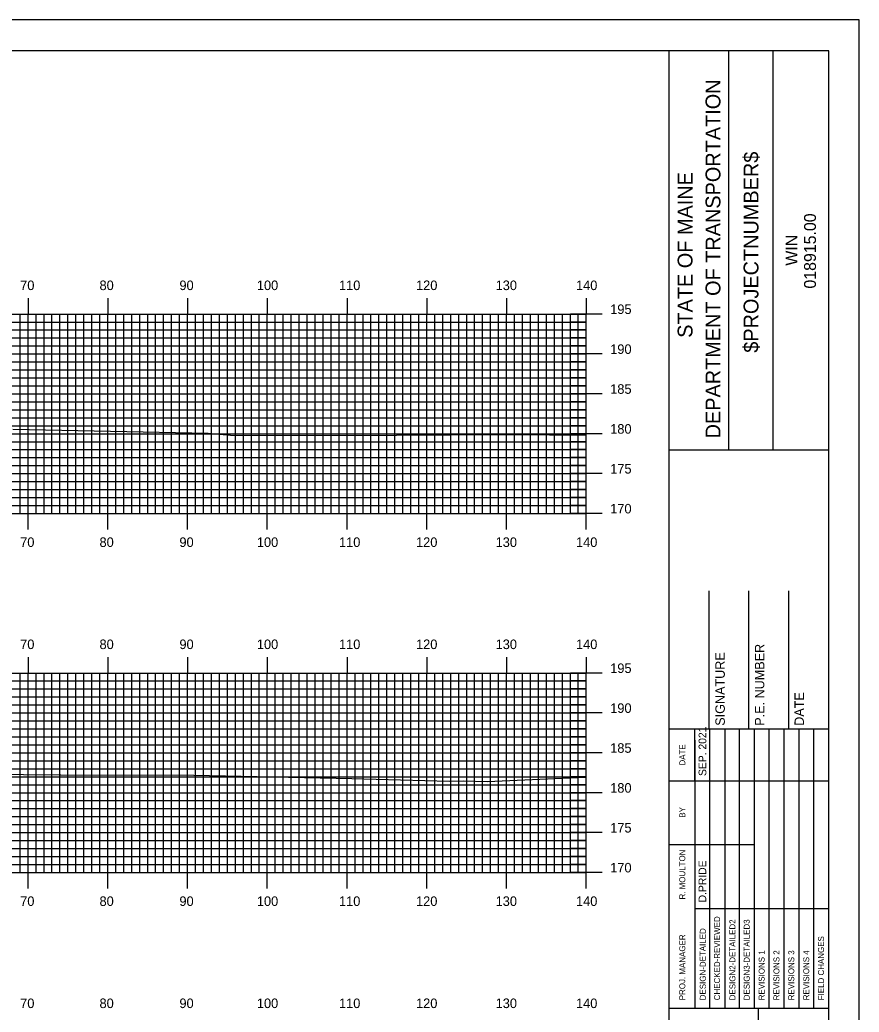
# Model space of a CAD drawing. Extents: x 1824360 to 1824703, y 442591 to 442811.
# Drawn here: x 1824594.3 to 1824699.5, y 442686.2 to 442810.5 of the extents above; entities that cross this region are included whole.
import ezdxf

# ---------------------------------------------------------------- set-up
doc = ezdxf.new("R2010")
doc.units = 0
for name, color, linetype in [('BORDER', 7, 'Continuous'), ('H_V ANNOTATION', 7, 'Continuous'), ('MAJOR', 7, 'Continuous'), ('MINOR', 7, 'Continuous'), ('PLOT BOUNDARY', 7, 'Continuous'), ('S_Roadway_Centerline', 7, 'Continuous')]:
    doc.layers.add(name, color=color, linetype=linetype)

msp = doc.modelspace()

# ---------------------------------------------------------------- linework, layer by layer
at = {"layer": 'BORDER'}
for p, q in [((1824675.73, 442596.67), (1824675.73, 442806.67)), ((1824683.19, 442756.66), (1824683.19, 442806.66)), ((1824688.78, 442756.66), (1824688.78, 442806.66)), ((1824675.74, 442756.65), (1824695.73, 442756.65)), ((1824680.73, 442721.67), (1824680.73, 442738.97)), ((1824685.73, 442721.67), (1824685.73, 442738.97)), ((1824690.73, 442721.67), (1824690.73, 442738.97)), ((1824675.73, 442721.67), (1824695.73, 442721.67)), ((1824675.73, 442686.67), (1824695.73, 442686.67)), ((1824686.92, 442616.67), (1824686.92, 442686.67))]:
    msp.add_line(p, q, dxfattribs=at)
msp.add_lwpolyline([(1824375.73, 442596.67), (1824695.73, 442596.67), (1824695.73, 442806.67), (1824375.73, 442806.67)], close=True, dxfattribs=at)
for points in [[(1824678.96, 442715.17), (1824678.96, 442721.67)], [(1824680.83, 442686.68), (1824680.83, 442721.67)], [(1824682.69, 442721.67), (1824682.69, 442686.68)], [(1824684.56, 442686.68), (1824684.56, 442721.67)], [(1824686.42, 442686.68), (1824686.42, 442721.67)], [(1824688.28, 442686.68), (1824688.28, 442721.67)], [(1824690.15, 442686.68), (1824690.15, 442721.67)], [(1824692.01, 442686.68), (1824692.01, 442721.67)], [(1824693.87, 442686.68), (1824693.87, 442721.67)], [(1824678.97, 442686.68), (1824678.97, 442720.26)], [(1824675.73, 442715.17), (1824695.73, 442715.17)], [(1824675.73, 442707.17), (1824678.97, 442707.17)], [(1824678.96, 442707.17), (1824686.42, 442707.17)], [(1824678.96, 442699.17), (1824695.73, 442699.17)]]:
    msp.add_lwpolyline(points, dxfattribs=at)
at = {"layer": 'MAJOR'}
for p, q in [((1824595.33, 442775.67), (1824595.33, 442773.67)), ((1824605.33, 442775.67), (1824605.33, 442773.67)), ((1824615.33, 442775.67), (1824615.33, 442773.67)), ((1824625.33, 442775.67), (1824625.33, 442773.67)), ((1824635.33, 442775.67), (1824635.33, 442773.67)), ((1824645.33, 442775.67), (1824645.33, 442773.67)), ((1824655.33, 442775.67), (1824655.33, 442773.67)), ((1824665.33, 442775.67), (1824665.33, 442773.67)), ((1824385.33, 442773.67), (1824665.33, 442773.67)), ((1824385.33, 442773.67), (1824665.33, 442773.67)), ((1824595.33, 442748.67), (1824595.33, 442773.67)), ((1824605.33, 442748.67), (1824605.33, 442773.67)), ((1824615.33, 442748.67), (1824615.33, 442773.67)), ((1824625.33, 442748.67), (1824625.33, 442773.67)), ((1824635.33, 442748.67), (1824635.33, 442773.67)), ((1824645.33, 442748.67), (1824645.33, 442773.67)), ((1824655.33, 442748.67), (1824655.33, 442773.67)), ((1824667.34, 442773.67), (1824663.33, 442773.67)), ((1824665.33, 442748.67), (1824665.33, 442773.67)), ((1824665.33, 442748.67), (1824665.33, 442773.67)), ((1824385.33, 442768.67), (1824665.33, 442768.67)), ((1824667.34, 442768.67), (1824663.33, 442768.67)), ((1824385.33, 442763.67), (1824665.33, 442763.67)), ((1824667.34, 442763.67), (1824663.33, 442763.67)), ((1824385.33, 442758.67), (1824665.33, 442758.67)), ((1824667.34, 442758.67), (1824663.33, 442758.67)), ((1824385.33, 442753.67), (1824665.33, 442753.67)), ((1824667.34, 442753.67), (1824663.33, 442753.67)), ((1824385.33, 442748.67), (1824665.33, 442748.67)), ((1824385.33, 442748.67), (1824665.33, 442748.67)), ((1824595.33, 442746.66), (1824595.33, 442748.67)), ((1824605.33, 442746.66), (1824605.33, 442748.67)), ((1824615.33, 442746.66), (1824615.33, 442748.67)), ((1824625.33, 442746.66), (1824625.33, 442748.67)), ((1824635.33, 442746.66), (1824635.33, 442748.67)), ((1824645.33, 442746.66), (1824645.33, 442748.67)), ((1824655.33, 442746.66), (1824655.33, 442748.67)), ((1824667.34, 442748.67), (1824663.33, 442748.67)), ((1824665.33, 442746.66), (1824665.33, 442748.67)), ((1824595.33, 442730.67), (1824595.33, 442728.67)), ((1824605.33, 442730.67), (1824605.33, 442728.67)), ((1824615.33, 442730.67), (1824615.33, 442728.67)), ((1824625.33, 442730.67), (1824625.33, 442728.67)), ((1824635.33, 442730.67), (1824635.33, 442728.67)), ((1824645.33, 442730.67), (1824645.33, 442728.67)), ((1824655.33, 442730.67), (1824655.33, 442728.67)), ((1824665.33, 442730.67), (1824665.33, 442728.67)), ((1824385.33, 442728.67), (1824665.33, 442728.67)), ((1824385.33, 442728.67), (1824665.33, 442728.67)), ((1824595.33, 442703.67), (1824595.33, 442728.67)), ((1824605.33, 442703.67), (1824605.33, 442728.67)), ((1824615.33, 442703.67), (1824615.33, 442728.67)), ((1824625.33, 442703.67), (1824625.33, 442728.67)), ((1824635.33, 442703.67), (1824635.33, 442728.67)), ((1824645.33, 442703.67), (1824645.33, 442728.67)), ((1824655.33, 442703.67), (1824655.33, 442728.67)), ((1824667.34, 442728.67), (1824663.33, 442728.67)), ((1824665.33, 442703.67), (1824665.33, 442728.67)), ((1824665.33, 442703.67), (1824665.33, 442728.67)), ((1824385.33, 442723.67), (1824665.33, 442723.67)), ((1824667.34, 442723.67), (1824663.33, 442723.67)), ((1824385.33, 442718.67), (1824665.33, 442718.67)), ((1824667.34, 442718.67), (1824663.33, 442718.67)), ((1824385.33, 442713.67), (1824665.33, 442713.67)), ((1824667.34, 442713.67), (1824663.33, 442713.67)), ((1824385.33, 442708.67), (1824665.33, 442708.67)), ((1824667.34, 442708.67), (1824663.33, 442708.67)), ((1824385.33, 442703.67), (1824665.33, 442703.67)), ((1824385.33, 442703.67), (1824665.33, 442703.67)), ((1824595.33, 442701.66), (1824595.33, 442703.67)), ((1824605.33, 442701.66), (1824605.33, 442703.67)), ((1824615.33, 442701.66), (1824615.33, 442703.67)), ((1824625.33, 442701.66), (1824625.33, 442703.67)), ((1824635.33, 442701.66), (1824635.33, 442703.67)), ((1824645.33, 442701.66), (1824645.33, 442703.67)), ((1824655.33, 442701.66), (1824655.33, 442703.67)), ((1824667.34, 442703.67), (1824663.33, 442703.67)), ((1824665.33, 442701.66), (1824665.33, 442703.67))]:
    msp.add_line(p, q, dxfattribs=at)
at = {"layer": 'MINOR'}
for p, q in [((1824594.33, 442748.67), (1824594.33, 442773.67)), ((1824596.33, 442748.67), (1824596.33, 442773.67)), ((1824597.33, 442748.67), (1824597.33, 442773.67)), ((1824598.33, 442748.67), (1824598.33, 442773.67)), ((1824599.33, 442748.67), (1824599.33, 442773.67)), ((1824600.33, 442748.67), (1824600.33, 442773.67)), ((1824601.33, 442748.67), (1824601.33, 442773.67)), ((1824602.33, 442748.67), (1824602.33, 442773.67)), ((1824603.33, 442748.67), (1824603.33, 442773.67)), ((1824604.33, 442748.67), (1824604.33, 442773.67)), ((1824606.33, 442748.67), (1824606.33, 442773.67)), ((1824607.33, 442748.67), (1824607.33, 442773.67)), ((1824608.33, 442748.67), (1824608.33, 442773.67)), ((1824609.33, 442748.67), (1824609.33, 442773.67)), ((1824610.33, 442748.67), (1824610.33, 442773.67)), ((1824611.33, 442748.67), (1824611.33, 442773.67)), ((1824612.33, 442748.67), (1824612.33, 442773.67)), ((1824613.33, 442748.67), (1824613.33, 442773.67)), ((1824614.33, 442748.67), (1824614.33, 442773.67)), ((1824616.33, 442748.67), (1824616.33, 442773.67)), ((1824617.33, 442748.67), (1824617.33, 442773.67)), ((1824618.33, 442748.67), (1824618.33, 442773.67)), ((1824619.33, 442748.67), (1824619.33, 442773.67)), ((1824620.33, 442748.67), (1824620.33, 442773.67)), ((1824621.33, 442748.67), (1824621.33, 442773.67)), ((1824622.33, 442748.67), (1824622.33, 442773.67)), ((1824623.33, 442748.67), (1824623.33, 442773.67)), ((1824624.33, 442748.67), (1824624.33, 442773.67)), ((1824626.33, 442748.67), (1824626.33, 442773.67)), ((1824627.33, 442748.67), (1824627.33, 442773.67)), ((1824628.33, 442748.67), (1824628.33, 442773.67)), ((1824629.33, 442748.67), (1824629.33, 442773.67)), ((1824630.33, 442748.67), (1824630.33, 442773.67)), ((1824631.33, 442748.67), (1824631.33, 442773.67)), ((1824632.33, 442748.67), (1824632.33, 442773.67)), ((1824633.33, 442748.67), (1824633.33, 442773.67)), ((1824634.33, 442748.67), (1824634.33, 442773.67)), ((1824636.33, 442748.67), (1824636.33, 442773.67)), ((1824637.33, 442748.67), (1824637.33, 442773.67)), ((1824638.33, 442748.67), (1824638.33, 442773.67)), ((1824639.33, 442748.67), (1824639.33, 442773.67)), ((1824640.33, 442748.67), (1824640.33, 442773.67)), ((1824641.33, 442748.67), (1824641.33, 442773.67)), ((1824642.33, 442748.67), (1824642.33, 442773.67)), ((1824643.33, 442748.67), (1824643.33, 442773.67)), ((1824644.33, 442748.67), (1824644.33, 442773.67)), ((1824646.33, 442748.67), (1824646.33, 442773.67)), ((1824647.33, 442748.67), (1824647.33, 442773.67)), ((1824648.33, 442748.67), (1824648.33, 442773.67)), ((1824649.33, 442748.67), (1824649.33, 442773.67)), ((1824650.33, 442748.67), (1824650.33, 442773.67)), ((1824651.33, 442748.67), (1824651.33, 442773.67)), ((1824652.33, 442748.67), (1824652.33, 442773.67)), ((1824653.33, 442748.67), (1824653.33, 442773.67)), ((1824654.33, 442748.67), (1824654.33, 442773.67)), ((1824656.33, 442748.67), (1824656.33, 442773.67)), ((1824657.33, 442748.67), (1824657.33, 442773.67)), ((1824658.33, 442748.67), (1824658.33, 442773.67)), ((1824659.33, 442748.67), (1824659.33, 442773.67)), ((1824660.33, 442748.67), (1824660.33, 442773.67)), ((1824661.33, 442748.67), (1824661.33, 442773.67)), ((1824662.33, 442748.67), (1824662.33, 442773.67)), ((1824663.33, 442748.67), (1824663.33, 442773.67)), ((1824664.33, 442748.67), (1824664.33, 442773.67)), ((1824385.33, 442772.67), (1824665.33, 442772.67)), ((1824665.33, 442772.67), (1824663.33, 442772.67)), ((1824385.33, 442771.67), (1824665.33, 442771.67)), ((1824665.33, 442771.67), (1824663.33, 442771.67)), ((1824385.33, 442770.67), (1824665.33, 442770.67)), ((1824665.33, 442770.67), (1824663.33, 442770.67)), ((1824385.33, 442769.67), (1824665.33, 442769.67)), ((1824665.33, 442769.67), (1824663.33, 442769.67)), ((1824385.33, 442767.67), (1824665.33, 442767.67)), ((1824665.33, 442767.67), (1824663.33, 442767.67)), ((1824385.33, 442766.67), (1824665.33, 442766.67)), ((1824665.33, 442766.67), (1824663.33, 442766.67)), ((1824385.33, 442765.67), (1824665.33, 442765.67)), ((1824665.33, 442765.67), (1824663.33, 442765.67)), ((1824385.33, 442764.67), (1824665.33, 442764.67)), ((1824665.33, 442764.67), (1824663.33, 442764.67)), ((1824385.33, 442762.67), (1824665.33, 442762.67)), ((1824665.33, 442762.67), (1824663.33, 442762.67)), ((1824385.33, 442761.67), (1824665.33, 442761.67)), ((1824665.33, 442761.67), (1824663.33, 442761.67)), ((1824385.33, 442760.67), (1824665.33, 442760.67)), ((1824665.33, 442760.67), (1824663.33, 442760.67)), ((1824385.33, 442759.67), (1824665.33, 442759.67)), ((1824665.33, 442759.67), (1824663.33, 442759.67)), ((1824385.33, 442757.67), (1824665.33, 442757.67)), ((1824665.33, 442757.67), (1824663.33, 442757.67)), ((1824385.33, 442756.67), (1824665.33, 442756.67)), ((1824665.33, 442756.67), (1824663.33, 442756.67)), ((1824385.33, 442755.67), (1824665.33, 442755.67)), ((1824665.33, 442755.67), (1824663.33, 442755.67)), ((1824385.33, 442754.67), (1824665.33, 442754.67)), ((1824665.33, 442754.67), (1824663.33, 442754.67)), ((1824385.33, 442752.67), (1824665.33, 442752.67)), ((1824665.33, 442752.67), (1824663.33, 442752.67)), ((1824385.33, 442751.67), (1824665.33, 442751.67)), ((1824665.33, 442751.67), (1824663.33, 442751.67)), ((1824385.33, 442750.67), (1824665.33, 442750.67)), ((1824665.33, 442750.67), (1824663.33, 442750.67)), ((1824385.33, 442749.67), (1824665.33, 442749.67)), ((1824665.33, 442749.67), (1824663.33, 442749.67)), ((1824385.33, 442727.67), (1824665.33, 442727.67)), ((1824594.33, 442703.67), (1824594.33, 442728.67)), ((1824596.33, 442703.67), (1824596.33, 442728.67)), ((1824597.33, 442703.67), (1824597.33, 442728.67)), ((1824598.33, 442703.67), (1824598.33, 442728.67)), ((1824599.33, 442703.67), (1824599.33, 442728.67)), ((1824600.33, 442703.67), (1824600.33, 442728.67)), ((1824601.33, 442703.67), (1824601.33, 442728.67)), ((1824602.33, 442703.67), (1824602.33, 442728.67)), ((1824603.33, 442703.67), (1824603.33, 442728.67)), ((1824604.33, 442703.67), (1824604.33, 442728.67)), ((1824606.33, 442703.67), (1824606.33, 442728.67)), ((1824607.33, 442703.67), (1824607.33, 442728.67)), ((1824608.33, 442703.67), (1824608.33, 442728.67)), ((1824609.33, 442703.67), (1824609.33, 442728.67)), ((1824610.33, 442703.67), (1824610.33, 442728.67)), ((1824611.33, 442703.67), (1824611.33, 442728.67)), ((1824612.33, 442703.67), (1824612.33, 442728.67)), ((1824613.33, 442703.67), (1824613.33, 442728.67)), ((1824614.33, 442703.67), (1824614.33, 442728.67)), ((1824616.33, 442703.67), (1824616.33, 442728.67)), ((1824617.33, 442703.67), (1824617.33, 442728.67)), ((1824618.33, 442703.67), (1824618.33, 442728.67)), ((1824619.33, 442703.67), (1824619.33, 442728.67)), ((1824620.33, 442703.67), (1824620.33, 442728.67)), ((1824621.33, 442703.67), (1824621.33, 442728.67)), ((1824622.33, 442703.67), (1824622.33, 442728.67)), ((1824623.33, 442703.67), (1824623.33, 442728.67)), ((1824624.33, 442703.67), (1824624.33, 442728.67)), ((1824626.33, 442703.67), (1824626.33, 442728.67)), ((1824627.33, 442703.67), (1824627.33, 442728.67)), ((1824628.33, 442703.67), (1824628.33, 442728.67)), ((1824629.33, 442703.67), (1824629.33, 442728.67)), ((1824630.33, 442703.67), (1824630.33, 442728.67)), ((1824631.33, 442703.67), (1824631.33, 442728.67)), ((1824632.33, 442703.67), (1824632.33, 442728.67)), ((1824633.33, 442703.67), (1824633.33, 442728.67)), ((1824634.33, 442703.67), (1824634.33, 442728.67)), ((1824636.33, 442703.67), (1824636.33, 442728.67)), ((1824637.33, 442703.67), (1824637.33, 442728.67)), ((1824638.33, 442703.67), (1824638.33, 442728.67)), ((1824639.33, 442703.67), (1824639.33, 442728.67)), ((1824640.33, 442703.67), (1824640.33, 442728.67)), ((1824641.33, 442703.67), (1824641.33, 442728.67)), ((1824642.33, 442703.67), (1824642.33, 442728.67)), ((1824643.33, 442703.67), (1824643.33, 442728.67)), ((1824644.33, 442703.67), (1824644.33, 442728.67)), ((1824646.33, 442703.67), (1824646.33, 442728.67)), ((1824647.33, 442703.67), (1824647.33, 442728.67)), ((1824648.33, 442703.67), (1824648.33, 442728.67)), ((1824649.33, 442703.67), (1824649.33, 442728.67)), ((1824650.33, 442703.67), (1824650.33, 442728.67)), ((1824651.33, 442703.67), (1824651.33, 442728.67)), ((1824652.33, 442703.67), (1824652.33, 442728.67)), ((1824653.33, 442703.67), (1824653.33, 442728.67)), ((1824654.33, 442703.67), (1824654.33, 442728.67)), ((1824656.33, 442703.67), (1824656.33, 442728.67)), ((1824657.33, 442703.67), (1824657.33, 442728.67)), ((1824658.33, 442703.67), (1824658.33, 442728.67)), ((1824659.33, 442703.67), (1824659.33, 442728.67)), ((1824660.33, 442703.67), (1824660.33, 442728.67)), ((1824661.33, 442703.67), (1824661.33, 442728.67)), ((1824662.33, 442703.67), (1824662.33, 442728.67)), ((1824663.33, 442703.67), (1824663.33, 442728.67)), ((1824665.33, 442727.67), (1824663.33, 442727.67)), ((1824664.33, 442703.67), (1824664.33, 442728.67)), ((1824385.33, 442726.67), (1824665.33, 442726.67)), ((1824665.33, 442726.67), (1824663.33, 442726.67)), ((1824385.33, 442725.67), (1824665.33, 442725.67)), ((1824665.33, 442725.67), (1824663.33, 442725.67)), ((1824385.33, 442724.67), (1824665.33, 442724.67)), ((1824665.33, 442724.67), (1824663.33, 442724.67)), ((1824385.33, 442722.67), (1824665.33, 442722.67)), ((1824665.33, 442722.67), (1824663.33, 442722.67)), ((1824385.33, 442721.67), (1824665.33, 442721.67)), ((1824665.33, 442721.67), (1824663.33, 442721.67)), ((1824385.33, 442720.67), (1824665.33, 442720.67)), ((1824665.33, 442720.67), (1824663.33, 442720.67)), ((1824385.33, 442719.67), (1824665.33, 442719.67)), ((1824665.33, 442719.67), (1824663.33, 442719.67)), ((1824385.33, 442717.67), (1824665.33, 442717.67)), ((1824665.33, 442717.67), (1824663.33, 442717.67)), ((1824385.33, 442716.67), (1824665.33, 442716.67)), ((1824665.33, 442716.67), (1824663.33, 442716.67)), ((1824385.33, 442715.67), (1824665.33, 442715.67)), ((1824665.33, 442715.67), (1824663.33, 442715.67)), ((1824385.33, 442714.67), (1824665.33, 442714.67)), ((1824665.33, 442714.67), (1824663.33, 442714.67)), ((1824385.33, 442712.67), (1824665.33, 442712.67)), ((1824665.33, 442712.67), (1824663.33, 442712.67)), ((1824385.33, 442711.67), (1824665.33, 442711.67)), ((1824665.33, 442711.67), (1824663.33, 442711.67)), ((1824385.33, 442710.67), (1824665.33, 442710.67)), ((1824665.33, 442710.67), (1824663.33, 442710.67)), ((1824385.33, 442709.67), (1824665.33, 442709.67)), ((1824665.33, 442709.67), (1824663.33, 442709.67)), ((1824385.33, 442707.67), (1824665.33, 442707.67)), ((1824385.33, 442706.67), (1824665.33, 442706.67)), ((1824665.33, 442707.67), (1824663.33, 442707.67)), ((1824665.33, 442706.67), (1824663.33, 442706.67)), ((1824385.33, 442705.67), (1824665.33, 442705.67)), ((1824665.33, 442705.67), (1824663.33, 442705.67)), ((1824385.33, 442704.67), (1824665.33, 442704.67)), ((1824665.33, 442704.67), (1824663.33, 442704.67))]:
    msp.add_line(p, q, dxfattribs=at)
at = {"layer": 'PLOT BOUNDARY'}
msp.add_lwpolyline([(1824359.55, 442590.55), (1824699.55, 442590.55), (1824699.55, 442810.55), (1824359.55, 442810.55)], close=True, dxfattribs=at)
at = {"layer": 'S_Roadway_Centerline'}
for points in [[(1824593.41, 442759.22), (1824617.91, 442758.72), (1824620.7, 442758.48), (1824628.31, 442758.45), (1824641.53, 442758.47), (1824654.95, 442758.57), (1824656.09, 442758.58), (1824665.33, 442758.49)], [(1824585.61, 442716.03), (1824599.32, 442715.92), (1824599.42, 442715.92), (1824616.11, 442715.85), (1824635.92, 442715.43), (1824648.15, 442715.13), (1824649.92, 442715.16), (1824652.88, 442715.08), (1824664.23, 442715.59), (1824665.33, 442715.62)]]:
    msp.add_lwpolyline(points, dxfattribs=at)

# ---------------------------------------------------------------- texts
at = {"layer": 'BORDER'}
for s, height, p in [('DEPARTMENT OF TRANSPORTATION', 1.8635, (1824682.15, 442758.08)), ('$PROJECTNUMBER$', 1.8635, (1824686.92, 442768.82)), ('STATE OF MAINE', 1.8635, (1824678.65, 442770.69)), ('018915.00', 1.491, (1824694.13, 442776.86)), ('WIN', 1.491, (1824691.81, 442779.73)), ('P.E. NUMBER', 1.1811, (1824687.66, 442722.06)), ('SIGNATURE', 1.181, (1824682.7, 442722.06)), ('DATE', 1.181, (1824692.62, 442722.06)), ('SEP. 2021', 0.969, (1824680.38, 442715.76)), ('DATE', 0.743, (1824677.74, 442717.08)), ('BY', 0.743, (1824677.74, 442710.54)), ('R. MOULTON', 0.745, (1824677.74, 442700.28)), ('D.PRIDE', 0.969, (1824680.38, 442699.92)), ('CHECKED-REVIEWED', 0.7455, (1824682.1, 442687.65)), ('DESIGN2-DETAILED2', 0.7455, (1824684.03, 442687.65)), ('DESIGN3-DETAILED3', 0.7455, (1824685.82, 442687.65)), ('DESIGN-DETAILED', 0.7455, (1824680.31, 442687.65)), ('PROJ. MANAGER', 0.7455, (1824677.74, 442687.65)), ('FIELD CHANGES', 0.7455, (1824695.14, 442687.65)), ('REVISIONS 1', 0.7455, (1824687.69, 442687.65)), ('REVISIONS 2', 0.7455, (1824689.55, 442687.65)), ('REVISIONS 3', 0.7455, (1824691.41, 442687.65)), ('REVISIONS 4', 0.7455, (1824693.28, 442687.65))]:
    msp.add_text(s, height=height, rotation=90, dxfattribs=at).set_placement(p)
at = {"layer": 'H_V ANNOTATION'}
for s, p in [('70', (1824594.34, 442776.67)), ('80', (1824604.29, 442776.67)), ('90', (1824614.31, 442776.67)), ('100', (1824624.02, 442776.67)), ('110', (1824634.32, 442776.67)), ('120', (1824643.98, 442776.67)), ('130', (1824653.96, 442776.67)), ('140', (1824664.04, 442776.67)), ('195', (1824668.33, 442773.67)), ('190', (1824668.33, 442768.67)), ('185', (1824668.33, 442763.67)), ('180', (1824668.33, 442758.67)), ('175', (1824668.33, 442753.67)), ('170', (1824668.33, 442748.67)), ('70', (1824594.34, 442744.47)), ('80', (1824604.29, 442744.47)), ('90', (1824614.31, 442744.47)), ('100', (1824624.02, 442744.47)), ('110', (1824634.32, 442744.47)), ('120', (1824643.98, 442744.47)), ('130', (1824653.96, 442744.47)), ('140', (1824664.04, 442744.47)), ('70', (1824594.34, 442731.67)), ('80', (1824604.29, 442731.67)), ('90', (1824614.31, 442731.67)), ('100', (1824624.02, 442731.67)), ('110', (1824634.32, 442731.67)), ('120', (1824643.98, 442731.67)), ('130', (1824653.96, 442731.67)), ('140', (1824664.04, 442731.67)), ('195', (1824668.33, 442728.67)), ('190', (1824668.33, 442723.67)), ('185', (1824668.33, 442718.67)), ('180', (1824668.33, 442713.67)), ('175', (1824668.33, 442708.67)), ('170', (1824668.33, 442703.67)), ('70', (1824594.34, 442699.47)), ('80', (1824604.29, 442699.47)), ('90', (1824614.31, 442699.47)), ('100', (1824624.02, 442699.47)), ('110', (1824634.32, 442699.47)), ('120', (1824643.98, 442699.47)), ('130', (1824653.96, 442699.47)), ('140', (1824664.04, 442699.47)), ('70', (1824594.34, 442686.67)), ('80', (1824604.29, 442686.67)), ('90', (1824614.31, 442686.67)), ('100', (1824624.02, 442686.67)), ('110', (1824634.32, 442686.67)), ('120', (1824643.98, 442686.67)), ('130', (1824653.96, 442686.67)), ('140', (1824664.04, 442686.67))]:
    msp.add_text(s, height=1.2, dxfattribs=at).set_placement(p)

doc.saveas('drawing.dxf')
